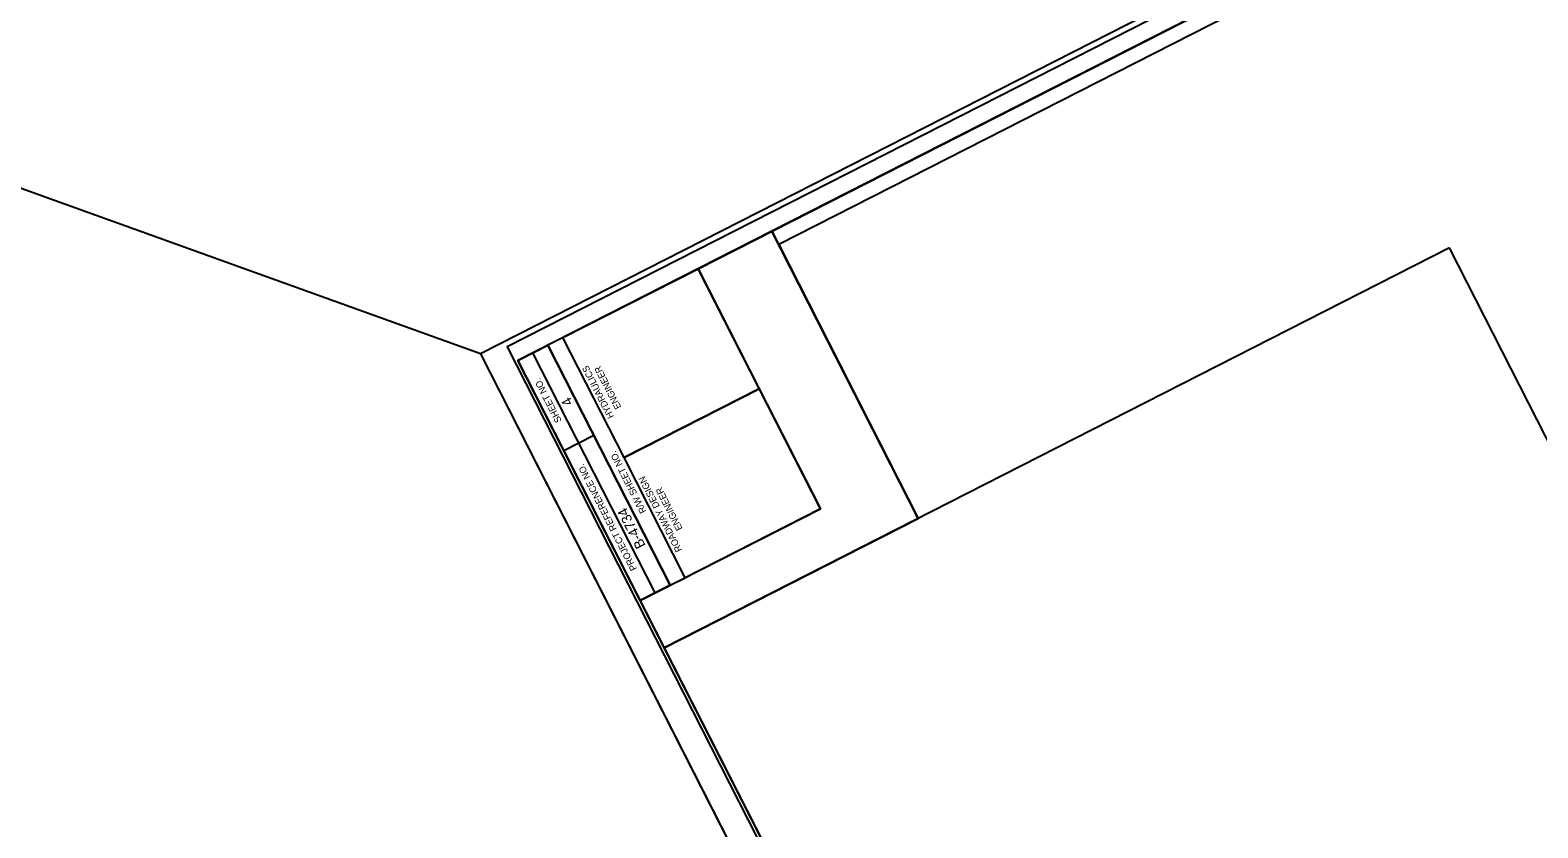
# Model space of a CAD drawing. Extents: x 556187 to 564861, y 510905 to 519096.
# Drawn here: x 558168 to 559286, y 515684 to 516276 of the extents above; entities that cross this region are included whole.
import ezdxf

# ---------------------------------------------------------------- set-up
doc = ezdxf.new("R2010")
doc.units = 0
for name, color, linetype in [('Cogo Default Point CELL', 7, 'Continuous'), ('Exist Environmental Wetland Boundary', 7, 'Continuous'), ('Exist Environmental Wetland Boundary Cogo Comment', 7, 'Continuous'), ('Exist Environmental Wetland Boundary Cogo Point CELL', 7, 'Continuous'), ('Exist Hydro Jurisdictional Stream or Body of Water NEU Mitigable', 7, 'Continuous'), ('Exist Hydro Jurisdictional Stream or Body of Water NEU Mitigable Cogo Elevation', 7, 'Continuous'), ('Exist Hydro Jurisdictional Stream or Body of Water NEU Mitigable Cogo Point CELL', 7, 'Continuous'), ('Exist Hydro Swamp or Marsh', 7, 'Continuous'), ('Sheet Cutting Line CELL', 7, 'Continuous')]:
    doc.layers.add(name, color=color, linetype=linetype)

msp = doc.modelspace()

# ---------------------------------------------------------------- linework, layer by layer
at = {"layer": 'Cogo Default Point CELL'}
for p, q in [((559220.7, 516114.5), (558638, 515817.8)), ((559328.6, 515902.5), (559220.7, 516114.5)), ((558638, 515817.8), (559199.4, 514715.3))]:
    msp.add_line(p, q, dxfattribs=at)
at = {"layer": 'Exist Environmental Wetland Boundary'}
msp.add_lwpolyline([(560217.6, 515035.1), (559461.7, 516519.7), (558521.5, 516041.1), (559277.4, 514556.4)], close=True, dxfattribs=at)
at = {"layer": 'Exist Environmental Wetland Boundary Cogo Comment'}
msp.add_lwpolyline([(560241.3, 515032.6), (559477.5, 516532.8), (558501.7, 516036), (559265.5, 514535.7)], close=True, dxfattribs=at)
at = {"layer": 'Exist Hydro Jurisdictional Stream or Body of Water NEU Mitigable'}
for p, q in [((558631.4, 515858.5), (558540.6, 516036.7)), ((558642.5, 515864.2), (558551.8, 516042.4)), ((558642.5, 515864.2), (558551.8, 516042.4)), ((558608.3, 515959), (558708.5, 516010)), ((558563.5, 515964.2), (558585.8, 515975.6)), ((558642.5, 515864.2), (558653.7, 515869.8))]:
    msp.add_line(p, q, dxfattribs=at)
for points in [[(558529.4, 516031.1), (559210, 514694.3), (560145.7, 515170.7), (559465.1, 516507.4)], [(560145.7, 515170.7), (559210, 514694.3), (558620.2, 515852.8), (558753.9, 515920.9), (558663.2, 516099.1), (559465.1, 516507.4)], [(558608.3, 515959), (558562.9, 516048.1), (558663.2, 516099.1), (558708.5, 516010)], [(558620.2, 515852.8), (558529.4, 516031.1), (558551.8, 516042.4), (558642.5, 515864.2)], [(558653.7, 515869.8), (558608.3, 515959), (558708.5, 516010), (558753.9, 515920.9)]]:
    msp.add_lwpolyline(points, close=True, dxfattribs=at)
at = {"layer": 'Exist Hydro Jurisdictional Stream or Body of Water NEU Mitigable Cogo Elevation'}
for p, q in [((559470.2, 516497.6), (558723, 516117.1)), ((558723, 516117.1), (558826.5, 515913.8)), ((558826.5, 515913.8), (558638, 515817.8)), ((558638, 515817.8), (559199.4, 514715.3))]:
    msp.add_line(p, q, dxfattribs=at)
at = {"layer": 'Exist Hydro Jurisdictional Stream or Body of Water NEU Mitigable Cogo Point CELL'}
msp.add_line((558501.7, 516036), (556187.1, 516868.1), dxfattribs=at)
at = {"layer": 'Exist Hydro Swamp or Marsh'}
for points in [[(559210, 514694.3), (560145.7, 515170.7), (559465.1, 516507.4), (558717.9, 516127), (558826.5, 515913.8), (558638, 515817.8)], [(558826.5, 515913.8), (558717.9, 516127), (558529.4, 516031.1), (558638, 515817.8)]]:
    msp.add_lwpolyline(points, close=True, dxfattribs=at)
at = {"layer": 'Sheet Cutting Line CELL'}
msp.add_line((558501.7, 516036), (559265.5, 514535.7), dxfattribs=at)

# ---------------------------------------------------------------- texts
at = {"layer": 'Exist Environmental Wetland Boundary Cogo Point CELL'}
for s, p in [('4  ', (558570.5, 515999.5)), ('B-4734   ', (558624.4, 515893.7))]:
    msp.add_text(s, height=7.5, rotation=116.9819, dxfattribs=at).set_placement(p)
at = {"layer": 'Exist Hydro Jurisdictional Stream or Body of Water NEU Mitigable'}
for s, p in [('HYDRAULICS', (558600.9, 515989.4)), ('ENGINEER', (558606.3, 515996.4)), ('SHEET NO.', (558562.1, 515986.3)), ('R/W SHEET NO.', (558624.9, 515919.1)), ('PROJECT REFERENCE NO.', (558617.9, 515876.5)), ('ROADWAY DESIGN', (558651.4, 515890.4)), ('ENGINEER', (558651.8, 515906.3))]:
    msp.add_text(s, height=5, rotation=116.9819, dxfattribs=at).set_placement(p)

doc.saveas('drawing.dxf')
